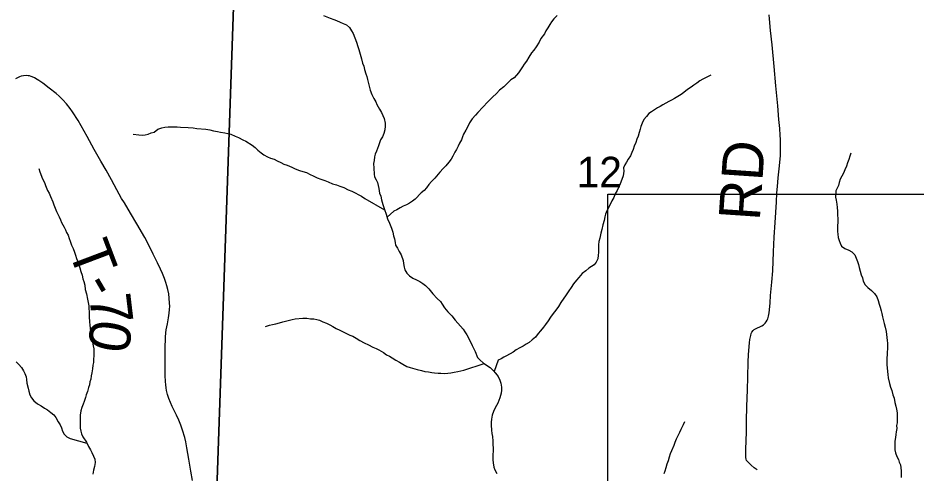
# Model space of a CAD drawing. Extents: x -3.3 to 34, y 0 to 56.8.
# Drawn here: x -0.562 to 0.677, y 32.719 to 33.346 of the extents above; entities that cross this region are included whole.
import ezdxf

# ---------------------------------------------------------------- set-up
doc = ezdxf.new("R2010")
doc.units = 0
for name, color, linetype in [('GM_X_Corporation', 7, 'Continuous'), ('GM_X_Section_Text', 7, 'Continuous'), ('GM_X_Township_Road', 7, 'Continuous'), ('GM_X_Township_Road_Text', 7, 'Continuous'), ('GT_Project_Soil_Layers', 7, 'Continuous'), ('SH_Major_Grid_Line', 7, 'Continuous')]:
    doc.layers.add(name, color=color, linetype=linetype)

msp = doc.modelspace()

# ---------------------------------------------------------------- linework, layer by layer
at = {"layer": 'GM_X_Corporation'}
for points in [[(-1.2628, 33.6793), (-0.2543, 33.6541), (-0.2878, 32.6826), (-1.3017, 32.7146)], [(-0.2543, 33.6541), (0.7743, 33.6261), (0.7357, 32.6242), (-0.2878, 32.6826)]]:
    msp.add_lwpolyline(points, close=True, dxfattribs=at)
at = {"layer": 'GM_X_Township_Road'}
for points in [[(0.4577, 32.7229), (0.4537, 32.726), (0.4495, 32.7295), (0.4465, 32.7327), (0.445, 32.7343), (0.4434, 32.7359), (0.4426, 32.7379), (0.4423, 32.7399), (0.4421, 32.7423), (0.4424, 32.7517), (0.443, 32.775), (0.4434, 32.7907), (0.4439, 32.8104), (0.4444, 32.8334), (0.4449, 32.8509), (0.4453, 32.872), (0.4459, 32.8815), (0.4463, 32.8877), (0.4474, 32.898), (0.448, 32.9028), (0.449, 32.9082), (0.4497, 32.9108), (0.4506, 32.9129), (0.4522, 32.9152), (0.4539, 32.9166), (0.4555, 32.9175), (0.4644, 32.9216), (0.4668, 32.9232), (0.4689, 32.9253), (0.4705, 32.9273), (0.4717, 32.9293), (0.4726, 32.9313), (0.4736, 32.9349), (0.4745, 32.9395), (0.4751, 32.9436), (0.4758, 32.9534), (0.4765, 32.9632), (0.4782, 32.9816), (0.4793, 32.9976), (0.4805, 33.0235), (0.4815, 33.0439), (0.4827, 33.0639), (0.4845, 33.0922), (0.4852, 33.1047), (0.4859, 33.1138), (0.4869, 33.1256), (0.4885, 33.1419), (0.4899, 33.1565), (0.4903, 33.1615), (0.4903, 33.1668), (0.4903, 33.1725), (0.4901, 33.1786), (0.4898, 33.1845), (0.4891, 33.1934), (0.4878, 33.2061), (0.4863, 33.2248), (0.4838, 33.2523), (0.4815, 33.2792), (0.4784, 33.309), (0.4763, 33.3288), (0.4749, 33.3446), (0.4744, 33.3504)], [(-0.321, 32.7086), (-0.3233, 32.7211), (-0.326, 32.7379), (-0.3285, 32.7536), (-0.3301, 32.7617), (-0.3314, 32.7679), (-0.3345, 32.7779), (-0.3368, 32.7847), (-0.3397, 32.7917), (-0.3428, 32.7987), (-0.3487, 32.8102), (-0.3513, 32.8158), (-0.3536, 32.8214), (-0.3552, 32.8269), (-0.3566, 32.8324), (-0.3573, 32.836), (-0.3577, 32.8401), (-0.358, 32.8448), (-0.3583, 32.8532), (-0.3585, 32.8819), (-0.3583, 32.8946), (-0.3581, 32.9015), (-0.3579, 32.9061), (-0.3574, 32.9118), (-0.3569, 32.9161), (-0.3554, 32.9242), (-0.354, 32.9326), (-0.3529, 32.9391), (-0.3524, 32.9439), (-0.3522, 32.9485), (-0.3523, 32.9527), (-0.3528, 32.9599), (-0.3536, 32.9658), (-0.3549, 32.9719), (-0.356, 32.9765), (-0.3575, 32.9812), (-0.3594, 32.9869), (-0.362, 32.9935), (-0.3649, 32.9996), (-0.369, 33.0083), (-0.3749, 33.0204), (-0.3801, 33.0311), (-0.3865, 33.0435), (-0.3977, 33.0624), (-0.4064, 33.0769), (-0.4148, 33.0909), (-0.4185, 33.0973), (-0.425, 33.1092), (-0.4325, 33.123), (-0.44, 33.136), (-0.4472, 33.1485), (-0.4565, 33.1646), (-0.4662, 33.1826), (-0.4787, 33.2044), (-0.4862, 33.2165), (-0.4894, 33.2213), (-0.4944, 33.2276), (-0.4995, 33.2332), (-0.5047, 33.238), (-0.509, 33.2418), (-0.5185, 33.2493), (-0.527, 33.2559), (-0.5326, 33.2599), (-0.5348, 33.2613), (-0.5386, 33.2635), (-0.5419, 33.2649), (-0.5434, 33.2654), (-0.5458, 33.266), (-0.5475, 33.2662), (-0.5499, 33.2664), (-0.554, 33.2661), (-0.5571, 33.2655), (-0.5593, 33.2647), (-0.5649, 33.2621)]]:
    msp.add_lwpolyline(points, dxfattribs=at)
at = {"layer": 'GT_Project_Soil_Layers'}
for points in [[(-0.1402, 33.3495), (-0.131, 33.3455), (-0.1261, 33.3437), (-0.1222, 33.3426), (-0.1173, 33.34), (-0.1131, 33.3381), (-0.1085, 33.3363), (-0.1043, 33.3326), (-0.1016, 33.3284), (-0.0992, 33.3243), (-0.0945, 33.3126), (-0.0926, 33.3065), (-0.0914, 33.3024), (-0.0878, 33.2895), (-0.0862, 33.2834), (-0.0846, 33.2797), (-0.0838, 33.2751), (-0.0818, 33.2691), (-0.0806, 33.2653), (-0.0794, 33.2611), (-0.0782, 33.2554), (-0.0758, 33.2464), (-0.0734, 33.2403)], [(0.1821, 33.3495), (0.1777, 33.3445), (0.1743, 33.3406), (0.1721, 33.3368), (0.1691, 33.3322), (0.1665, 33.3284), (0.1647, 33.3242), (0.1598, 33.3177), (0.1572, 33.3127), (0.1532, 33.3062), (0.1498, 33.3016), (0.1468, 33.2977), (0.1431, 33.292), (0.1398, 33.2866), (0.1368, 33.2824), (0.1342, 33.2785), (0.129, 33.2705), (0.123, 33.2636), (0.1181, 33.2605), (0.1125, 33.2551), (0.1084, 33.2512), (0.1028, 33.2466)], [(0.3941, 33.267), (0.3903, 33.2654), (0.3828, 33.2615), (0.379, 33.2592), (0.3749, 33.2561), (0.3708, 33.2533), (0.367, 33.2506), (0.3618, 33.2471), (0.3569, 33.2433), (0.3531, 33.2406), (0.3486, 33.2375), (0.3441, 33.2351), (0.34, 33.2328), (0.3362, 33.2308), (0.3279, 33.2262), (0.3242, 33.2238), (0.3204, 33.2219), (0.3163, 33.2195), (0.3121, 33.2164), (0.3084, 33.2141), (0.3054, 33.2103), (0.3017, 33.206), (0.2991, 33.2007), (0.2976, 33.1965), (0.2965, 33.1927), (0.2951, 33.1881), (0.2936, 33.1831), (0.2918, 33.1789), (0.2907, 33.1744), (0.2885, 33.169), (0.2871, 33.1648), (0.2852, 33.1606), (0.2834, 33.156), (0.2801, 33.1514), (0.2775, 33.1472), (0.2756, 33.1434), (0.2738, 33.1392), (0.2742, 33.1346), (0.2732, 33.1285), (0.2713, 33.1232), (0.2692, 33.1171), (0.2647, 33.1079), (0.2621, 33.1033), (0.2603, 33.0987), (0.2573, 33.0937), (0.2551, 33.0888), (0.2507, 33.0803), (0.2489, 33.0757), (0.2478, 33.0719), (0.2467, 33.067), (0.2453, 33.0609), (0.2435, 33.0544), (0.2424, 33.0494), (0.241, 33.0426), (0.2395, 33.0376), (0.2392, 33.0331), (0.2393, 33.0274), (0.239, 33.0228), (0.2387, 33.019), (0.238, 33.0141), (0.2358, 33.0095), (0.2332, 33.0056), (0.2294, 33.0033), (0.2256, 33.0013), (0.2215, 32.9975), (0.2166, 32.9936), (0.2118, 32.9882), (0.2088, 32.9844), (0.2047, 32.9794), (0.2014, 32.9744), (0.198, 32.9698), (0.1947, 32.9644), (0.1872, 32.9537), (0.1839, 32.9483), (0.1802, 32.9433), (0.1768, 32.9384), (0.1731, 32.9334), (0.1698, 32.9284), (0.166, 32.9234), (0.1631, 32.9196), (0.1593, 32.9149), (0.156, 32.9111), (0.1523, 32.9061), (0.1478, 32.9022), (0.1433, 32.8988), (0.1395, 32.8961), (0.1354, 32.8937), (0.1308, 32.8914), (0.1256, 32.8883), (0.1214, 32.8855), (0.1124, 32.8801), (0.1086, 32.8785), (0.1049, 32.8762), (0.1007, 32.8742), (0.0951, 32.8587)], [(0.1028, 33.2466), (0.0983, 33.2416), (0.0931, 33.2366), (0.0867, 33.2304), (0.0725, 33.2158), (0.0695, 33.2119), (0.065, 33.2069), (0.0613, 33.2015), (0.0587, 33.1962), (0.0562, 33.1912), (0.0528, 33.1859), (0.0514, 33.182), (0.0503, 33.1778), (0.0473, 33.1732), (0.0455, 33.1694), (0.0433, 33.1648), (0.041, 33.161), (0.0381, 33.1556), (0.0359, 33.1514), (0.0325, 33.1472), (0.0284, 33.1422), (0.0247, 33.1384), (0.0202, 33.1334), (0.0135, 33.1249), (0.0086, 33.1203), (0.0052, 33.1164), (0.0019, 33.1118), (-0.0015, 33.108), (-0.0056, 33.1049), (-0.0138, 33.0964), (-0.0176, 33.0933), (-0.0217, 33.0906), (-0.0258, 33.0883), (-0.0304, 33.0863), (-0.0345, 33.0843), (-0.039, 33.0816), (-0.0432, 33.0797), (-0.0525, 33.0714)], [(-0.0734, 33.2403), (-0.0707, 33.2347), (-0.068, 33.2305), (-0.0664, 33.2267), (-0.0629, 33.2203), (-0.0602, 33.2158), (-0.0582, 33.2113), (-0.0563, 33.2075), (-0.0551, 33.2011), (-0.055, 33.1969), (-0.0557, 33.1919), (-0.0568, 33.1866), (-0.059, 33.182), (-0.0616, 33.1778), (-0.0641, 33.1698), (-0.0671, 33.1625), (-0.0689, 33.1583), (-0.07, 33.1545), (-0.0703, 33.1496), (-0.071, 33.1454), (-0.0709, 33.1389), (-0.0704, 33.1306), (-0.0696, 33.1268), (-0.0673, 33.123), (-0.0657, 33.1192), (-0.0649, 33.1151), (-0.0637, 33.1109), (-0.0628, 33.1045), (-0.0609, 33.1003), (-0.0601, 33.0954), (-0.0581, 33.089), (-0.0561, 33.0821), (-0.0537, 33.0753), (-0.0517, 33.0689), (-0.049, 33.0633), (-0.0462, 33.0561), (-0.0443, 33.0508), (-0.0434, 33.0455), (-0.0422, 33.0413), (-0.0414, 33.0364), (-0.041, 33.0326), (-0.0379, 33.0285), (-0.0356, 33.0239), (-0.0328, 33.0194), (-0.0305, 33.0115), (-0.0296, 33.0077), (-0.0288, 33.0024), (-0.028, 32.9986), (-0.0253, 32.9944), (-0.0214, 32.9903), (-0.0169, 32.9873), (-0.0119, 32.9851), (-0.0073, 32.9825), (-0.0031, 32.9799), (0.0007, 32.9773), (0.005, 32.9724), (0.0107, 32.9657), (0.0165, 32.9593), (0.0211, 32.9552), (0.0235, 32.9514), (0.0266, 32.9465), (0.0312, 32.9409), (0.037, 32.9353), (0.0416, 32.9296), (0.0524, 32.9169), (0.0547, 32.9131), (0.0574, 32.909), (0.0601, 32.9041), (0.0648, 32.8943), (0.0691, 32.886), (0.0723, 32.878), (0.0757, 32.8743), (0.0799, 32.8705), (0.0845, 32.8676), (0.0895, 32.8642), (0.0937, 32.8601), (0.0972, 32.8563), (0.1007, 32.8518), (0.103, 32.8465), (0.1046, 32.8428), (0.1054, 32.8371), (0.1055, 32.8329), (0.1048, 32.8287), (0.103, 32.8222), (0.1001, 32.815), (0.0967, 32.8088), (0.0945, 32.8035), (0.0923, 32.7985), (0.0916, 32.7928), (0.0909, 32.7886), (0.091, 32.7848), (0.0915, 32.778), (0.0919, 32.7734), (0.0927, 32.7689), (0.0936, 32.7625), (0.0938, 32.7484), (0.0934, 32.7446), (0.0932, 32.737), (0.094, 32.7328), (0.0948, 32.7268), (0.096, 32.723)], [(-0.4026, 33.1856), (-0.395, 33.1849), (-0.39, 33.1846), (-0.3859, 33.185), (-0.3821, 33.1859), (-0.3779, 33.1874), (-0.3738, 33.1886), (-0.3685, 33.1925), (-0.3629, 33.1945), (-0.3591, 33.1953), (-0.3542, 33.1957), (-0.342, 33.1959), (-0.3375, 33.1956), (-0.3269, 33.195), (-0.32, 33.1943), (-0.3147, 33.1936), (-0.3026, 33.1927), (-0.2969, 33.1916), (-0.2919, 33.1905), (-0.2862, 33.1895), (-0.2824, 33.1884), (-0.276, 33.1877), (-0.268, 33.1856), (-0.2619, 33.183), (-0.2573, 33.1811), (-0.2515, 33.1778), (-0.2474, 33.176), (-0.2386, 33.1704), (-0.2343, 33.1674), (-0.2305, 33.1637), (-0.2263, 33.1599), (-0.2224, 33.1573), (-0.2175, 33.1544), (-0.2133, 33.1529), (-0.2083, 33.1511), (-0.2041, 33.1488), (-0.1988, 33.1466), (-0.195, 33.1444), (-0.1904, 33.143), (-0.1839, 33.1404), (-0.1793, 33.1378), (-0.1732, 33.1356), (-0.1687, 33.1345), (-0.1637, 33.1327), (-0.1587, 33.1301), (-0.1546, 33.1283), (-0.1488, 33.1257), (-0.1439, 33.1239), (-0.1385, 33.122), (-0.1336, 33.1202), (-0.1275, 33.1172), (-0.1221, 33.1158), (-0.1176, 33.1143), (-0.1122, 33.1121), (-0.1061, 33.1092), (-0.1012, 33.107), (-0.0966, 33.1051), (-0.0916, 33.1022), (-0.0878, 33.1003), (-0.0832, 33.0973), (-0.0559, 33.0817)], [(0.5871, 33.1598), (0.5856, 33.1553), (0.5845, 33.1507), (0.5827, 33.1461), (0.5813, 33.1415), (0.5787, 33.1366), (0.5768, 33.132), (0.5746, 33.1281), (0.5724, 33.1236), (0.571, 33.119), (0.5699, 33.1152), (0.5684, 33.1113), (0.5666, 33.1075), (0.5659, 33.0988), (0.5667, 33.095), (0.5676, 33.0893), (0.5684, 33.0847), (0.5688, 33.0798), (0.5691, 33.0642), (0.5687, 33.06), (0.5689, 33.0517), (0.5693, 33.0479), (0.5697, 33.0433), (0.5709, 33.0392), (0.5725, 33.0354), (0.5744, 33.0316), (0.579, 33.0283), (0.5844, 33.0257), (0.5886, 33.0235), (0.5924, 33.0193), (0.5964, 33.0103), (0.5979, 33.0061), (0.5987, 33.0019), (0.6015, 32.9921), (0.6031, 32.9879), (0.6043, 32.983), (0.607, 32.9781), (0.6105, 32.9744), (0.6155, 32.9703), (0.6197, 32.9661), (0.6228, 32.9616), (0.6248, 32.9567), (0.6264, 32.9514), (0.6276, 32.9473), (0.6288, 32.9423), (0.63, 32.9385), (0.6308, 32.934), (0.6316, 32.9302), (0.6332, 32.9249), (0.6344, 32.9196), (0.636, 32.9136), (0.6364, 32.9098), (0.6373, 32.9014), (0.6377, 32.8976), (0.6378, 32.8931), (0.6372, 32.882), (0.6369, 32.8771), (0.6366, 32.8733), (0.6366, 32.8683), (0.6375, 32.8585), (0.638, 32.8547), (0.6388, 32.8498), (0.6404, 32.8422), (0.642, 32.8369), (0.6436, 32.8323), (0.6452, 32.8263), (0.6467, 32.8221), (0.648, 32.8161), (0.6492, 32.8108), (0.65, 32.8066), (0.6508, 32.8017), (0.651, 32.788), (0.6503, 32.7842), (0.6504, 32.78), (0.6497, 32.7754), (0.649, 32.7716), (0.6486, 32.7678), (0.648, 32.7625), (0.648, 32.7572), (0.6477, 32.7507), (0.6489, 32.7466), (0.6505, 32.7416), (0.6529, 32.7375), (0.6537, 32.7337), (0.6556, 32.7299), (0.656, 32.7261), (0.6565, 32.7216), (0.6566, 32.7125)], [(-0.5327, 33.1386), (-0.5315, 33.134), (-0.5276, 33.1242), (-0.5249, 33.1193), (-0.5233, 33.1151), (-0.5206, 33.1083), (-0.5186, 33.1046), (-0.5167, 33.1), (-0.5135, 33.0925), (-0.5119, 33.0883), (-0.5084, 33.0793), (-0.5065, 33.0755), (-0.5049, 33.0717), (-0.5029, 33.0679), (-0.5014, 33.0642), (-0.4979, 33.0578), (-0.4959, 33.054), (-0.4944, 33.0502), (-0.4924, 33.0464), (-0.4908, 33.0419), (-0.4893, 33.0381), (-0.4877, 33.0328), (-0.4853, 33.0283), (-0.4837, 33.023), (-0.4822, 33.0188), (-0.4806, 33.0143), (-0.479, 33.0102), (-0.4774, 33.0056), (-0.4762, 33.0015), (-0.475, 32.9965), (-0.4731, 32.9916), (-0.4719, 32.9863), (-0.4707, 32.9825), (-0.4695, 32.9776), (-0.4686, 32.9716), (-0.467, 32.9659), (-0.4654, 32.9583), (-0.4638, 32.9492), (-0.4637, 32.945), (-0.4633, 32.9412), (-0.4632, 32.9344), (-0.4627, 32.9268), (-0.4626, 32.923), (-0.4618, 32.9177), (-0.461, 32.9109), (-0.4594, 32.9041), (-0.4577, 32.8942), (-0.4569, 32.8897), (-0.4567, 32.8802), (-0.4574, 32.8756), (-0.4574, 32.871), (-0.4581, 32.8672), (-0.4588, 32.8623), (-0.4595, 32.8566), (-0.4605, 32.8528), (-0.4612, 32.8482), (-0.4623, 32.8444), (-0.463, 32.8402), (-0.4641, 32.8364), (-0.4655, 32.831), (-0.4674, 32.8265), (-0.4685, 32.8227), (-0.4703, 32.8173), (-0.4718, 32.8135), (-0.4736, 32.8089), (-0.475, 32.8043), (-0.4757, 32.7986), (-0.4755, 32.7804), (-0.4747, 32.7766), (-0.4738, 32.7728), (-0.4719, 32.7687), (-0.4672, 32.7611), (-0.4641, 32.7551), (-0.4614, 32.7506), (-0.4595, 32.7468), (-0.4571, 32.7419), (-0.4555, 32.7377), (-0.4551, 32.7332), (-0.4558, 32.7275), (-0.4572, 32.7225), (-0.4583, 32.7172)], [(-0.2199, 32.9207), (-0.2146, 32.9223), (-0.2105, 32.9235), (-0.206, 32.9243), (-0.2007, 32.9259), (-0.1961, 32.9271), (-0.1924, 32.9279), (-0.1871, 32.9295), (-0.1833, 32.9303), (-0.1791, 32.9311), (-0.1685, 32.932), (-0.1632, 32.9321), (-0.1579, 32.9314), (-0.1533, 32.9311), (-0.1495, 32.9304), (-0.1457, 32.9293), (-0.1412, 32.9271), (-0.1362, 32.9253), (-0.1312, 32.9231), (-0.1274, 32.9208), (-0.1228, 32.9179), (-0.1175, 32.9157), (-0.1129, 32.9131), (-0.1037, 32.9086), (-0.0999, 32.9072), (-0.0953, 32.9046), (-0.09, 32.9016), (-0.0839, 32.8983), (-0.0781, 32.8953), (-0.072, 32.8924), (-0.0675, 32.8905), (-0.0636, 32.8883), (-0.0575, 32.885), (-0.0533, 32.8816), (-0.0491, 32.8798), (-0.0453, 32.8775), (-0.0403, 32.8742), (-0.0353, 32.8716), (-0.0308, 32.8686), (-0.025, 32.8657), (-0.0208, 32.8642), (-0.0109, 32.8613), (-0.0052, 32.8599), (-0.0003, 32.8588), (0.0047, 32.8581), (0.0092, 32.8574), (0.013, 32.8567), (0.018, 32.8564), (0.0217, 32.8564), (0.0271, 32.8561), (0.0354, 32.857), (0.0399, 32.8578), (0.0452, 32.8587), (0.0494, 32.8595), (0.0532, 32.8603), (0.0814, 32.8696)], [(-0.5639, 32.8718), (-0.5605, 32.8681), (-0.5566, 32.8643), (-0.5539, 32.8598), (-0.552, 32.8557), (-0.5504, 32.8511), (-0.5496, 32.8474), (-0.5491, 32.8424), (-0.5475, 32.8356), (-0.5467, 32.8314), (-0.5451, 32.8265), (-0.5428, 32.8224), (-0.5397, 32.8182), (-0.5347, 32.8141), (-0.5294, 32.8112), (-0.5248, 32.8082), (-0.5206, 32.8056), (-0.516, 32.8022), (-0.5121, 32.7989), (-0.5094, 32.7951), (-0.5059, 32.7895), (-0.5032, 32.7853), (-0.5016, 32.7812), (-0.5001, 32.7762), (-0.4977, 32.7725), (-0.4939, 32.7687), (-0.4897, 32.7665), (-0.4667, 32.7601)], [(0.3579, 32.7893), (0.3557, 32.7851), (0.3527, 32.7789), (0.3509, 32.7744), (0.3479, 32.769), (0.3461, 32.7652), (0.3446, 32.761), (0.3428, 32.7568), (0.3399, 32.7491), (0.338, 32.7453), (0.3366, 32.7407), (0.3351, 32.7354), (0.3333, 32.7308), (0.3318, 32.7259), (0.3304, 32.7213), (0.3293, 32.7175)], [(0.096, 32.723), (0.0987, 32.7181)]]:
    msp.add_lwpolyline(points, dxfattribs=at)
at = {"layer": 'SH_Major_Grid_Line'}
msp.add_lwpolyline([(0.2521, 33.103), (1.7872, 33.103), (1.7872, 32.5355), (0.2521, 32.5355)], close=True, dxfattribs=at)

# ---------------------------------------------------------------- texts
at = {"layer": 'GM_X_Section_Text'}
msp.add_text('12', height=0.04186, rotation=0, dxfattribs=at).set_placement((0.2091, 33.1127))
at = {"layer": 'GM_X_Township_Road_Text'}
for s, height, rotation, p in [('RD', 0.05682, 86.1209, (0.4614, 33.0656)), ('T', 0.0568, 290.7191, (-0.4928, 33.0266)), ('-', 0.0568, 300.4438, (-0.4732, 32.9774)), ('7', 0.0568, 276.7655, (-0.4634, 32.9631)), ('0', 0.0568, 260.8756, (-0.4592, 32.9325))]:
    msp.add_text(s, height=height, rotation=rotation, dxfattribs=at).set_placement(p)

doc.saveas('drawing.dxf')
